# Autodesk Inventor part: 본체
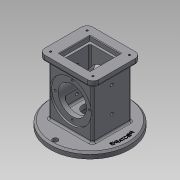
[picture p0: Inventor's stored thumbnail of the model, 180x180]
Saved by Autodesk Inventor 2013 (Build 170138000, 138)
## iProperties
Created: 2019-08
Part Number: 본체
Material: 일반
Document SubType Name: Modeling
Designer: Administrator
Density: 1 g/cm^3
Author: Administrator
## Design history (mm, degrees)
sketch "스케치1"
  geometry: C1 r 67.5 at (0, 0); 1 further point
  constraints: 1 centre point, 1 coincident
  dimensions: "d0" = 135 diameter of C1
extrude "돌출1" new body sketch "스케치1" distance "d2" = 10; taper "d3" = 0 deg
sketch "스케치2"
  geometry: L1 (-37, 33)-(37, 33); L2 (37, 33)-(37, -33); L3 (37, -33)-(-37, -33); L4 (-37, -33)-(-37, 33); L5 (-37, 33)-(37, -33); L6 (37, 33)-(-37, -33); 1 further point
  constraints: 12 end point, 2 midpoint, 2 parallel, 1 horizontal, 1 perpendicular
  dimensions: "d4" = 74 distance of L1.start L1.end; "d6" = 66 distance of L1.end L2.end
extrude "돌출2" join sketch "스케치2" distance "d7" = 98; taper "d8" = 0 deg
sketch "스케치4"
  geometry: L1 (-46, 41)-(46, 41); L2 (46, 41)-(46, -41); L3 (46, -41)-(-46, -41); L4 (-46, -41)-(-46, 41); L5 (-46, 41)-(46, -41); L6 (46, 41)-(-46, -41); 1 further point
  constraints: 12 end point, 2 midpoint, 2 parallel, 1 horizontal, 1 perpendicular
  dimensions: "d9" = 92 distance of L1.start L1.end; "d11" = 82 distance of L1.end L2.end
extrude "돌출3" join sketch "스케치4" distance "d12" = 10; taper "d13" = 0 deg
sketch "스케치5"
  geometry: L1 (-30.5, -10)-(104.5, -10) reference; C1 r 24 at (37, 44); 2 further points
  constraints: 1 centre point, 1 midpoint, 1 vertical alignment
  dimensions: "d14" = 48 diameter of C1; "d16" = 54 distance from line of L1 C1.centre
extrude "돌출4" cut sketch "스케치5" stored distance "d17" = 10; taper "d18" = 0 deg
sketch "스케치6"
  geometry: C1 r 24 at (37, 44) reference; C2 r 35 at (37, 44); 1 further point
  constraints: 1 centre point, 1 coincident
  dimensions: "d19" = 70 diameter of C2
extrude "돌출5" cut sketch "스케치6" distance "d21" = 3; taper "d22" = 0 deg
sketch "스케치7"
  geometry: L1 (-22, 22)-(22, 22); L2 (22, 22)-(22, -22); L3 (22, -22)-(-22, -22); L4 (-22, -22)-(-22, 22); L5 (-22, 22)-(22, -22); L6 (22, 22)-(-22, -22); 1 further point
  constraints: 12 end point, 2 midpoint, 2 parallel, 2 perpendicular, 1 horizontal
  dimensions: "d23" = 44 distance of L1.start L1.end
extrude "돌출6" cut sketch "스케치7" distance "d25" = 82; taper "d26" = 0 deg
fillet "모깎기1" dims "d27" = 3
fillet "모깎기2" dims "d28" = 3
sketch "스케치8"
  geometry: L1 (41, 98)-(33, 98) reference; L2 (33, 98)-(33, 89) reference; L3 (33, 89)-(30, 89) reference; L4 (30, 89)-(30, 78) reference; L5 (30, 78)-(22, 78) reference; L6 (22, 78)-(22, 108) reference; L7 (22, 108)-(41, 108) reference; L8 (41, 108)-(41, 98) reference; L9 (-33, 98)-(-41, 98) reference; L10 (-41, 98)-(-41, 108) reference; L11 (-41, 108)-(-22, 108) reference; L12 (-22, 108)-(-22, 78) reference; L13 (-22, 78)-(-30, 78) reference; L14 (-30, 78)-(-30, 89) reference; L15 (-30, 89)-(-33, 89) reference; L16 (-33, 89)-(-33, 98) reference; L17 (67.5, 10)-(67.5, 0) reference; L18 (67.5, 0)-(-67.5, 0) reference; L19 (-67.5, 0)-(-67.5, 10) reference; L20 (-67.5, 10)-(-33, 10) reference; L21 (-33, 10)-(-33, 19) reference; L22 (-33, 19)-(-30, 19) reference; L23 (-30, 19)-(-30, 30) reference; L24 (-30, 30)-(-22, 30) reference; L25 (-22, 30)-(-22, 29) reference; L26 (-19, 26)-(19, 26) reference; L27 (22, 29)-(22, 30) reference; L28 (22, 30)-(30, 30) reference; L29 (30, 30)-(30, 19) reference; L30 (30, 19)-(33, 19) reference; L31 (33, 19)-(33, 10) reference; L32 (33, 10)-(67.5, 10) reference; L33 (0, 0)-(0, 26); L34 (-25, 0)-(-25, 15); L35 (-22, 18)-(-12.5, 18); L36 (-12.5, 18)-(-12.5, 26); A1 r 3 centre (-19, 29) between (-22, 29) and (-19, 26) reference; A2 r 3 centre (19, 29) between (19, 26) and (22, 29) reference; A3 r 3 centre (-22, 15) between (-22, 18) and (-25, 15); 1 further point
  constraints: 8 end point, 4 point on line, 2 perpendicular, 2 point on circle, 2 tangent, 1 centre point, 1 midpoint, 1 parallel
  dimensions: "d29" = 50 diameter of L34 L33; "d31" = 25 diameter of L36 L33; "d32" = 18 distance between parallel lines of L18 L35; "d34" = 3 radius of A3
revolve "회전1" sketch "스케치8" stored, may be unused: angle "d33" = 90 deg
fillet "모깎기3" dims "d35" = 10
sketch "스케치11"
  geometry: L1 (10, -34.5)-(10, 100.5) reference; 3 further points
  constraints: 2 horizontal alignment
  dimensions: "d46" = 37 distance from line of point (-27, 33) L1; "d47" = 43 distance of point (-70, 33) point (-27, 33)
hole "구멍2" sketch "스케치11" at (-70, 33), (-27, 33) diameter "d48" = 4.917; stored, may be unused: countersink angle "d52" = 90 deg, drill point angle "d54" = 118 deg; dims "d49" = 4, "d50" = 4, "d51" = 2, "d53" = 6
sketch "스케치13"
  geometry: C1 r 24 at (0, 0) reference; 2 further points
  constraints: 1 vertical alignment
  dimensions: "d57" = 29 distance of C1.centre point (0, 29)
hole "구멍3" sketch "스케치13" at (0, 29) diameter "d58" = 3.242; stored, may be unused: countersink angle "d62" = 90 deg, drill point angle "d64" = 118 deg; dims "d59" = 4, "d60" = 4, "d61" = 2, "d63" = 6
sketch "스케치14"
  geometry: C1 r 67.5 at (0, 0) reference; 1 further point
  constraints: 1 vertical alignment
  dimensions: "d68" = 59 distance of C1.centre point (0, 59)
hole "구멍4" sketch "스케치14" at (0, 59) diameter "d69" = 9; stored, may be unused: countersink angle "d73" = 90 deg, drill point angle "d75" = 118 deg; dims "d70" = 4, "d71" = 4, "d72" = 2, "d74" = 6
node "작업 평면1"
sketch "스케치15"
  geometry: C1 r 59 at (0, 0); 1 further point
  constraints: 1 centre point, 1 coincident, 1 other
  dimensions: "d80" = 118 diameter of C1
feature "엠보싱1" sketch "스케치15" dims "d82" = 0.5, "d83" = 0
fillet "모깎기5" dims "d85" = 3
fillet "모깎기6" dims "d86" = 3
fillet "모깎기7" dims "d87" = 3
fillet "모깎기8" dims "d88" = 3
sketch "스케치17"
  geometry: L1 (-22, -19)-(-22, 19) reference; L2 (-19, 22)-(19, 22) reference; L3 (22, 19)-(22, -19) reference; L4 (19, -22)-(-19, -22) reference; L5 (-26, 26)-(26, 26); L6 (26, 26)-(26, -26); L7 (26, -26)-(-26, -26); L8 (-26, -26)-(-26, 26); L9 (-26, 26)-(26, -26); L10 (26, 26)-(-26, -26); A1 r 3 centre (-19, 19) between (-19, 22) and (-22, 19) reference; A2 r 3 centre (19, 19) between (22, 19) and (19, 22) reference; A3 r 3 centre (19, -19) between (19, -22) and (22, -19) reference; A4 r 3 centre (-19, -19) between (-22, -19) and (-19, -22) reference; 1 further point
  constraints: 12 end point, 2 midpoint, 2 parallel, 2 perpendicular, 1 horizontal
  dimensions: "d89" = 52 distance of L5.start L5.end
extrude "돌출7" cut sketch "스케치17" distance "d91" = 8; taper "d92" = 0 deg
chamfer "모따기2" distance "d93" = 1; stored, may be unused: second distance "d94" = 2, angle "d95" = 45 deg
chamfer "모따기3" distance "d96" = 3; stored, may be unused: second distance "d97" = 2, angle "d98" = 45 deg
sketch "스케치19"
  geometry: A1 r 10 centre (-36, -31) between (-46, -31) and (-36, -41) reference; A2 r 10 centre (36, -31) between (36, -41) and (46, -31) reference; A3 r 10 centre (36, 31) between (46, 31) and (36, 41) reference; A4 r 10 centre (-36, 31) between (-36, 41) and (-46, 31) reference; 1 further point
hole "구멍6" sketch "스케치19" at (36, 31), (-36, 31), (-36, -31), (36, -31) diameter "d106" = 3.242; stored, may be unused: countersink angle "d110" = 90 deg, drill point angle "d112" = 118 deg; dims "d107" = 4, "d108" = 4, "d109" = 2, "d111" = 6
node "솔리드1"
mirror "대칭1"
pattern_circular "원형 패턴1" dims angle "d66" = 360 deg
mirror "대칭2"
pattern_circular "원형 패턴2" dims angle "d77" = 180 deg
node "절단 모서리 투영1"
other parameters: "d79" = 33.5
